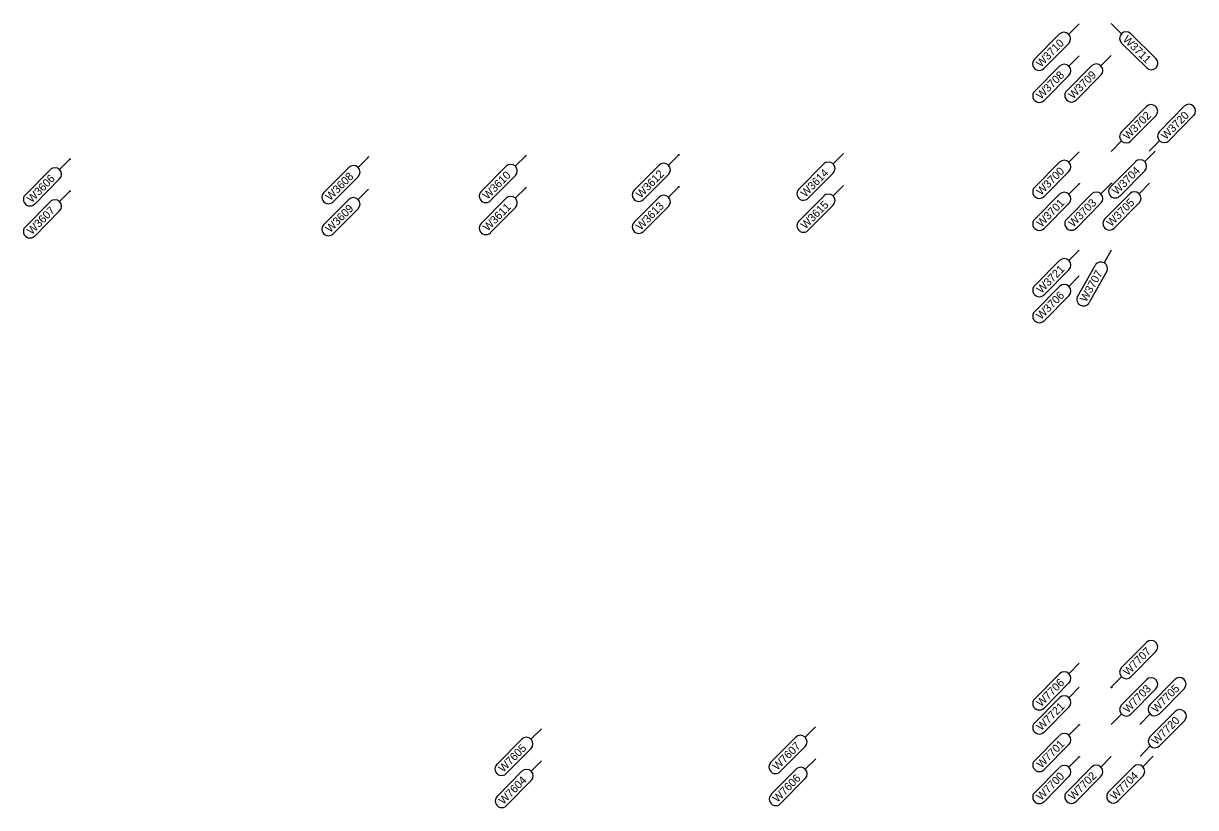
# Model space of a CAD drawing. Extents: x 12479652 to 12487250, y 9842710 to 9846560.
# Drawn here: x 12486293.6 to 12486476.7, y 9842770.2 to 9842892.6 of the extents above; entities that cross this region are included whole.
import ezdxf

# ---------------------------------------------------------------- set-up
doc = ezdxf.new("R2010")
doc.units = 0
doc.layers.add('_CIVIL_CONSTRUCTION', color=7, linetype='Continuous')
doc.layers.add('TextAlignmentLrg', color=7, linetype='Continuous')

msp = doc.modelspace()

# ---------------------------------------------------------------- linework, layer by layer
at = {"layer": '_CIVIL_CONSTRUCTION'}
for p, q in [((12486458.46, 9842892.6), (12486456.84, 9842890.97)), ((12486463.46, 9842892.64), (12486465.09, 9842891.02)), ((12486451.5, 9842887.05), (12486455.38, 9842890.97)), ((12486465.1, 9842889.57), (12486469.03, 9842885.7)), ((12486470.47, 9842887.16), (12486466.55, 9842891.03)), ((12486456.84, 9842889.52), (12486452.95, 9842885.61)), ((12486451.53, 9842882.05), (12486455.42, 9842885.97)), ((12486456.53, 9842882.09), (12486460.42, 9842886)), ((12486458.49, 9842887.6), (12486456.87, 9842885.97)), ((12486463.49, 9842887.64), (12486461.87, 9842886.01)), ((12486456.88, 9842884.52), (12486452.99, 9842880.61)), ((12486461.88, 9842884.56), (12486457.99, 9842880.64)), ((12486468.98, 9842879.65), (12486465.1, 9842875.73)), ((12486474.9, 9842879.7), (12486471.02, 9842875.77)), ((12486466.56, 9842874.29), (12486470.44, 9842878.21)), ((12486472.48, 9842874.33), (12486476.36, 9842878.26)), ((12486463.49, 9842872.64), (12486465.11, 9842874.28)), ((12486469.42, 9842872.68), (12486471.03, 9842874.32)), ((12486300.86, 9842871.44), (12486299.24, 9842869.81)), ((12486347.48, 9842871.78), (12486345.86, 9842870.15)), ((12486372.04, 9842871.96), (12486370.42, 9842870.33)), ((12486395.95, 9842872.14), (12486394.33, 9842870.51)), ((12486421.68, 9842872.33), (12486420.05, 9842870.7)), ((12486458.49, 9842872.6), (12486456.87, 9842870.97)), ((12486470.34, 9842872.69), (12486468.72, 9842871.06)), ((12486293.9, 9842865.89), (12486297.79, 9842869.8)), ((12486340.52, 9842866.23), (12486344.41, 9842870.15)), ((12486365.08, 9842866.41), (12486368.97, 9842870.33)), ((12486388.99, 9842866.59), (12486392.88, 9842870.5)), ((12486414.71, 9842866.78), (12486418.6, 9842870.69)), ((12486451.53, 9842867.05), (12486455.42, 9842870.97)), ((12486456.88, 9842869.52), (12486452.99, 9842865.61)), ((12486463.38, 9842867.14), (12486467.27, 9842871.05)), ((12486468.72, 9842869.61), (12486464.83, 9842865.69)), ((12486299.25, 9842868.36), (12486295.36, 9842864.44)), ((12486345.86, 9842868.7), (12486341.97, 9842864.79)), ((12486370.43, 9842868.88), (12486366.54, 9842864.97)), ((12486394.34, 9842869.06), (12486390.45, 9842865.15)), ((12486420.06, 9842869.25), (12486416.17, 9842865.34)), ((12486458.49, 9842867.6), (12486456.87, 9842865.97)), ((12486463.49, 9842867.64), (12486461.87, 9842866.01)), ((12486469.46, 9842867.68), (12486467.83, 9842866.05)), ((12486300.86, 9842866.44), (12486299.24, 9842864.81)), ((12486347.48, 9842866.78), (12486345.86, 9842865.15)), ((12486372.04, 9842866.96), (12486370.42, 9842865.33)), ((12486395.95, 9842867.14), (12486394.33, 9842865.51)), ((12486421.68, 9842867.33), (12486420.05, 9842865.7)), ((12486451.53, 9842862.05), (12486455.42, 9842865.97)), ((12486456.53, 9842862.09), (12486460.42, 9842866)), ((12486462.49, 9842862.13), (12486466.38, 9842866.05)), ((12486293.9, 9842860.89), (12486297.79, 9842864.8)), ((12486340.52, 9842861.23), (12486344.41, 9842865.15)), ((12486365.08, 9842861.41), (12486368.97, 9842865.33)), ((12486388.99, 9842861.59), (12486392.88, 9842865.5)), ((12486394.34, 9842864.06), (12486390.45, 9842860.14)), ((12486414.71, 9842861.78), (12486418.6, 9842865.69)), ((12486420.06, 9842864.25), (12486416.17, 9842860.34)), ((12486456.88, 9842864.52), (12486452.99, 9842860.61)), ((12486461.88, 9842864.56), (12486457.99, 9842860.64)), ((12486467.84, 9842864.6), (12486463.95, 9842860.69)), ((12486299.25, 9842863.36), (12486295.36, 9842859.44)), ((12486345.86, 9842863.7), (12486341.97, 9842859.79)), ((12486370.43, 9842863.88), (12486366.54, 9842859.97)), ((12486458.49, 9842857.25), (12486456.87, 9842855.62)), ((12486463.49, 9842857.25), (12486462.36, 9842855.25)), ((12486451.53, 9842851.7), (12486455.42, 9842855.61)), ((12486458.25, 9842850.06), (12486460.96, 9842854.86)), ((12486456.88, 9842854.17), (12486452.99, 9842850.26)), ((12486458.49, 9842853.21), (12486456.87, 9842851.58)), ((12486462.75, 9842853.85), (12486460.03, 9842849.05)), ((12486451.53, 9842847.66), (12486455.42, 9842851.57)), ((12486456.88, 9842850.12), (12486452.99, 9842846.21)), ((12486468.98, 9842795.98), (12486465.1, 9842792.05)), ((12486466.56, 9842790.61), (12486470.44, 9842794.54)), ((12486458.49, 9842792.72), (12486456.87, 9842791.09)), ((12486451.53, 9842787.17), (12486455.42, 9842791.08)), ((12486456.88, 9842789.64), (12486452.99, 9842785.72)), ((12486458.49, 9842788.96), (12486456.87, 9842787.33)), ((12486463.49, 9842788.96), (12486465.11, 9842790.6)), ((12486468.98, 9842790.15), (12486465.1, 9842786.22)), ((12486473.42, 9842790.18), (12486469.55, 9842786.26)), ((12486451.53, 9842783.41), (12486455.42, 9842787.33)), ((12486466.56, 9842784.78), (12486470.44, 9842788.71)), ((12486471.01, 9842784.82), (12486474.88, 9842788.74)), ((12486456.88, 9842785.88), (12486452.99, 9842781.97)), ((12486463.49, 9842783.14), (12486465.11, 9842784.77)), ((12486467.94, 9842783.17), (12486469.56, 9842784.81)), ((12486473.46, 9842785.18), (12486469.58, 9842781.26)), ((12486471.04, 9842779.82), (12486474.92, 9842783.74)), ((12486374.49, 9842782.48), (12486372.87, 9842780.85)), ((12486417.29, 9842782.8), (12486415.67, 9842781.16)), ((12486458.49, 9842783.1), (12486456.87, 9842781.47)), ((12486367.53, 9842776.93), (12486371.42, 9842780.84)), ((12486410.33, 9842777.25), (12486414.22, 9842781.16)), ((12486451.53, 9842777.55), (12486455.42, 9842781.46)), ((12486456.88, 9842780.02), (12486452.99, 9842776.1)), ((12486467.98, 9842778.17), (12486469.59, 9842779.81)), ((12486372.88, 9842779.4), (12486368.99, 9842775.48)), ((12486415.68, 9842779.71), (12486411.79, 9842775.8)), ((12486458.49, 9842778.1), (12486456.87, 9842776.47)), ((12486463.49, 9842778.14), (12486461.87, 9842776.51)), ((12486470.05, 9842778.19), (12486468.42, 9842776.55)), ((12486374.53, 9842777.48), (12486372.91, 9842775.85)), ((12486410.37, 9842772.25), (12486414.26, 9842776.16)), ((12486417.33, 9842777.8), (12486415.71, 9842776.16)), ((12486451.53, 9842772.55), (12486455.42, 9842776.46)), ((12486456.53, 9842772.59), (12486460.42, 9842776.5)), ((12486463.08, 9842772.64), (12486466.97, 9842776.55)), ((12486367.57, 9842771.93), (12486371.46, 9842775.84)), ((12486372.91, 9842774.4), (12486369.02, 9842770.48)), ((12486415.71, 9842774.71), (12486411.82, 9842770.8)), ((12486456.88, 9842775.02), (12486452.99, 9842771.1)), ((12486461.88, 9842775.05), (12486457.99, 9842771.14)), ((12486468.43, 9842775.1), (12486464.54, 9842771.19))]:
    msp.add_line(p, q, dxfattribs=at)
for centre, start, end in [((12486456.11, 9842890.24), 315.1702, 135.1702), ((12486465.82, 9842890.3), 45.3788, 225.3788), ((12486452.22, 9842886.33), 135.1702, 315.1702), ((12486456.15, 9842885.24), 315.1702, 135.1702), ((12486461.15, 9842885.28), 315.1702, 135.1702), ((12486469.75, 9842886.43), 225.3788, 45.3788), ((12486452.26, 9842881.33), 135.1702, 315.1702), ((12486457.26, 9842881.37), 135.1702, 315.1702), ((12486469.71, 9842878.93), 315.3788, 135.3788), ((12486475.63, 9842878.98), 315.3788, 135.3788), ((12486465.83, 9842875.01), 135.3788, 315.3788), ((12486471.75, 9842875.05), 135.3788, 315.3788), ((12486456.15, 9842870.24), 315.1702, 135.1702), ((12486467.99, 9842870.33), 315.1702, 135.1702), ((12486298.52, 9842869.08), 315.1702, 135.1702), ((12486345.14, 9842869.42), 315.1702, 135.1702), ((12486369.7, 9842869.6), 315.1702, 135.1702), ((12486393.61, 9842869.78), 315.1702, 135.1702), ((12486419.33, 9842869.97), 315.1702, 135.1702), ((12486294.63, 9842865.17), 135.1702, 315.1702), ((12486341.25, 9842865.51), 135.1702, 315.1702), ((12486365.81, 9842865.69), 135.1702, 315.1702), ((12486389.72, 9842865.87), 135.1702, 315.1702), ((12486393.61, 9842864.78), 315.1702, 135.1702), ((12486415.44, 9842866.06), 135.1702, 315.1702), ((12486419.33, 9842864.97), 315.1702, 135.1702), ((12486452.26, 9842866.33), 135.1702, 315.1702), ((12486456.15, 9842865.24), 315.1702, 135.1702), ((12486461.15, 9842865.28), 315.1702, 135.1702), ((12486464.1, 9842866.42), 135.1702, 315.1702), ((12486467.11, 9842865.32), 315.1702, 135.1702), ((12486298.52, 9842864.08), 315.1702, 135.1702), ((12486345.14, 9842864.42), 315.1702, 135.1702), ((12486369.7, 9842864.6), 315.1702, 135.1702), ((12486463.22, 9842861.41), 135.1702, 315.1702), ((12486294.63, 9842860.17), 135.1702, 315.1702), ((12486341.25, 9842860.51), 135.1702, 315.1702), ((12486365.81, 9842860.69), 135.1702, 315.1702), ((12486389.72, 9842860.87), 135.1702, 315.1702), ((12486415.44, 9842861.06), 135.1702, 315.1702), ((12486452.26, 9842861.33), 135.1702, 315.1702), ((12486457.26, 9842861.37), 135.1702, 315.1702), ((12486456.15, 9842854.89), 315.1702, 135.1702), ((12486461.86, 9842854.35), 330.5132, 150.5132), ((12486452.26, 9842850.98), 135.1702, 315.1702), ((12486456.15, 9842850.85), 315.1702, 135.1702), ((12486459.14, 9842849.55), 150.5132, 330.5132), ((12486452.26, 9842846.93), 135.1702, 315.1702), ((12486469.71, 9842795.26), 315.3788, 135.3788), ((12486456.15, 9842790.36), 315.1702, 135.1702), ((12486465.83, 9842791.33), 135.3788, 315.3788), ((12486469.71, 9842789.43), 315.3788, 135.3788), ((12486474.15, 9842789.46), 315.3788, 135.3788), ((12486452.26, 9842786.45), 135.1702, 315.1702), ((12486456.15, 9842786.6), 315.1702, 135.1702), ((12486465.83, 9842785.5), 135.3788, 315.3788), ((12486470.28, 9842785.54), 135.3788, 315.3788), ((12486474.19, 9842784.46), 315.3788, 135.3788), ((12486452.26, 9842782.69), 135.1702, 315.1702), ((12486456.15, 9842780.74), 315.1702, 135.1702), ((12486372.15, 9842780.12), 315.1702, 135.1702), ((12486414.95, 9842780.44), 315.1702, 135.1702), ((12486470.31, 9842780.54), 135.3788, 315.3788), ((12486368.26, 9842776.21), 135.1702, 315.1702), ((12486372.19, 9842775.12), 315.1702, 135.1702), ((12486411.06, 9842776.52), 135.1702, 315.1702), ((12486414.98, 9842775.44), 315.1702, 135.1702), ((12486452.26, 9842776.83), 135.1702, 315.1702), ((12486456.15, 9842775.74), 315.1702, 135.1702), ((12486461.15, 9842775.78), 315.1702, 135.1702), ((12486467.7, 9842775.83), 315.1702, 135.1702), ((12486452.26, 9842771.83), 135.1702, 315.1702), ((12486457.26, 9842771.86), 135.1702, 315.1702), ((12486463.81, 9842771.91), 135.1702, 315.1702), ((12486368.3, 9842771.21), 135.1702, 315.1702), ((12486411.1, 9842771.52), 135.1702, 315.1702)]:
    msp.add_arc(centre, 1.03, start, end, dxfattribs=at)
at = {"layer": 'TextAlignmentLrg'}
for centre in [(12486300.86, 9842871.44), (12486347.48, 9842871.78), (12486372.05, 9842871.96), (12486395.95, 9842872.14), (12486458.49, 9842867.6), (12486463.49, 9842867.64), (12486300.86, 9842866.44), (12486372.05, 9842866.96), (12486395.95, 9842867.14), (12486463.53, 9842788.93), (12486458.49, 9842783.1), (12486458.49, 9842778.1)]:
    msp.add_circle(centre, 0.05, dxfattribs=at)

# ---------------------------------------------------------------- texts
at = {"layer": '_CIVIL_CONSTRUCTION'}
for s, rotation, p in [('W3710', 45.1702, (12486452.49, 9842885.7)), ('W3711', 315.3788, (12486465.21, 9842890.02)), ('W3708', 45.1702, (12486452.53, 9842880.7)), ('W3709', 45.1702, (12486457.53, 9842880.74)), ('W3702', 45.3788, (12486466.1, 9842874.38)), ('W3720', 45.3788, (12486472.01, 9842874.4)), ('W3610', 45.1702, (12486366.08, 9842865.06)), ('W3612', 45.1702, (12486390.01, 9842865.26)), ('W3614', 45.1702, (12486415.71, 9842865.42)), ('W3700', 45.1702, (12486452.53, 9842865.7)), ('W3704', 45.1702, (12486464.37, 9842865.78)), ('W3606', 45.1702, (12486294.9, 9842864.54)), ('W3608', 45.1702, (12486341.52, 9842864.88)), ('W3607', 45.1702, (12486294.91, 9842859.55)), ('W3609', 45.1702, (12486341.52, 9842859.88)), ('W3611', 45.1702, (12486366.12, 9842860.1)), ('W3613', 45.1702, (12486390, 9842860.25)), ('W3615', 45.1702, (12486415.73, 9842860.44)), ('W3701', 45.1702, (12486452.57, 9842860.74)), ('W3703', 45.1702, (12486457.54, 9842860.75)), ('W3705', 45.1702, (12486463.5, 9842860.8)), ('W3721', 45.1702, (12486452.57, 9842850.39)), ('W3707', 60.5132, (12486459.58, 9842849.03)), ('W3706', 45.1702, (12486452.53, 9842846.3)), ('W7707', 45.3788, (12486466.09, 9842790.69)), ('W7706', 45.1702, (12486452.53, 9842785.82)), ('W7703', 45.3788, (12486466.09, 9842784.86)), ('W7705', 45.3788, (12486470.54, 9842784.9)), ('W7721', 45.1702, (12486452.57, 9842782.1)), ('W7720', 45.3788, (12486470.56, 9842779.89)), ('W7605', 45.1702, (12486368.54, 9842775.59)), ('W7607', 45.1702, (12486411.34, 9842775.91)), ('W7701', 45.1702, (12486452.57, 9842776.24)), ('W7604', 45.1702, (12486368.56, 9842770.57)), ('W7606', 45.1702, (12486411.36, 9842770.89)), ('W7700', 45.1702, (12486452.53, 9842771.2)), ('W7702', 45.1702, (12486457.55, 9842771.26)), ('W7704', 45.1702, (12486464.08, 9842771.28))]:
    msp.add_text(s, height=1.25, rotation=rotation, dxfattribs=at).set_placement(p)

doc.saveas('drawing.dxf')
